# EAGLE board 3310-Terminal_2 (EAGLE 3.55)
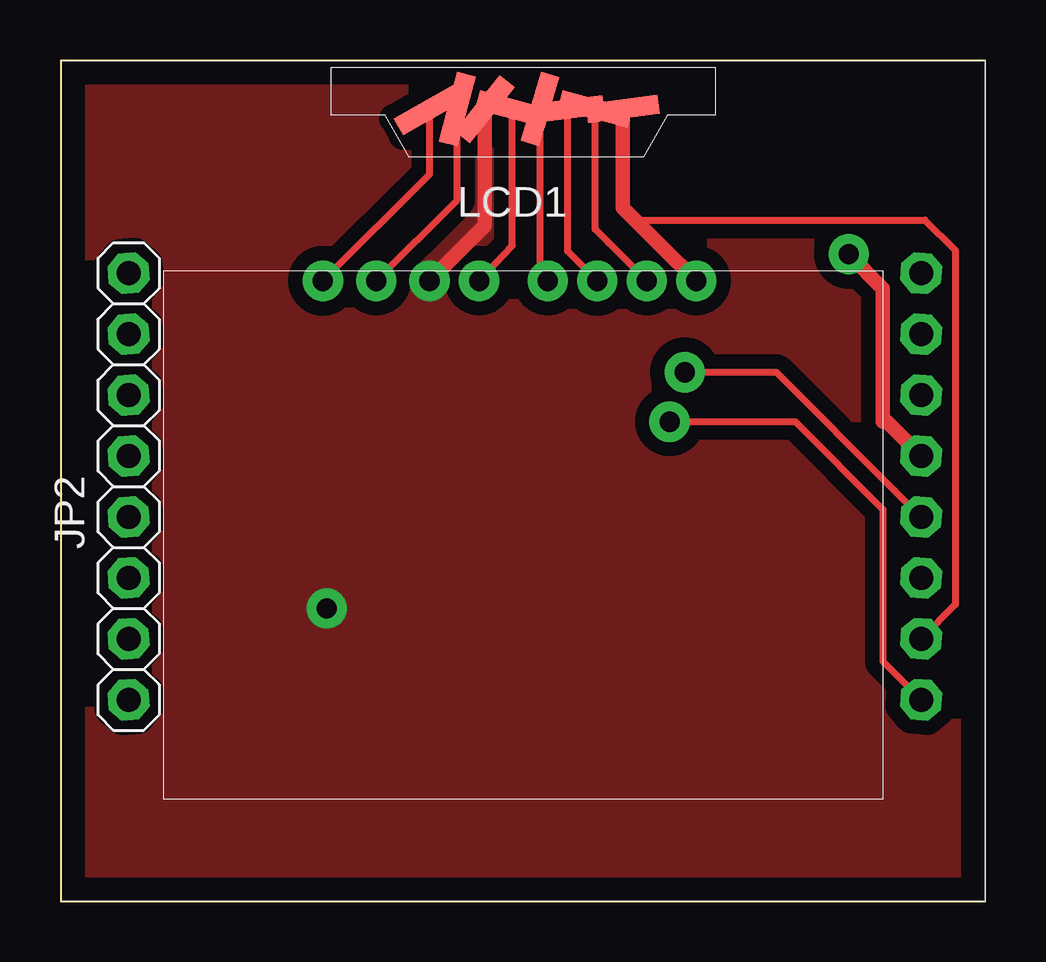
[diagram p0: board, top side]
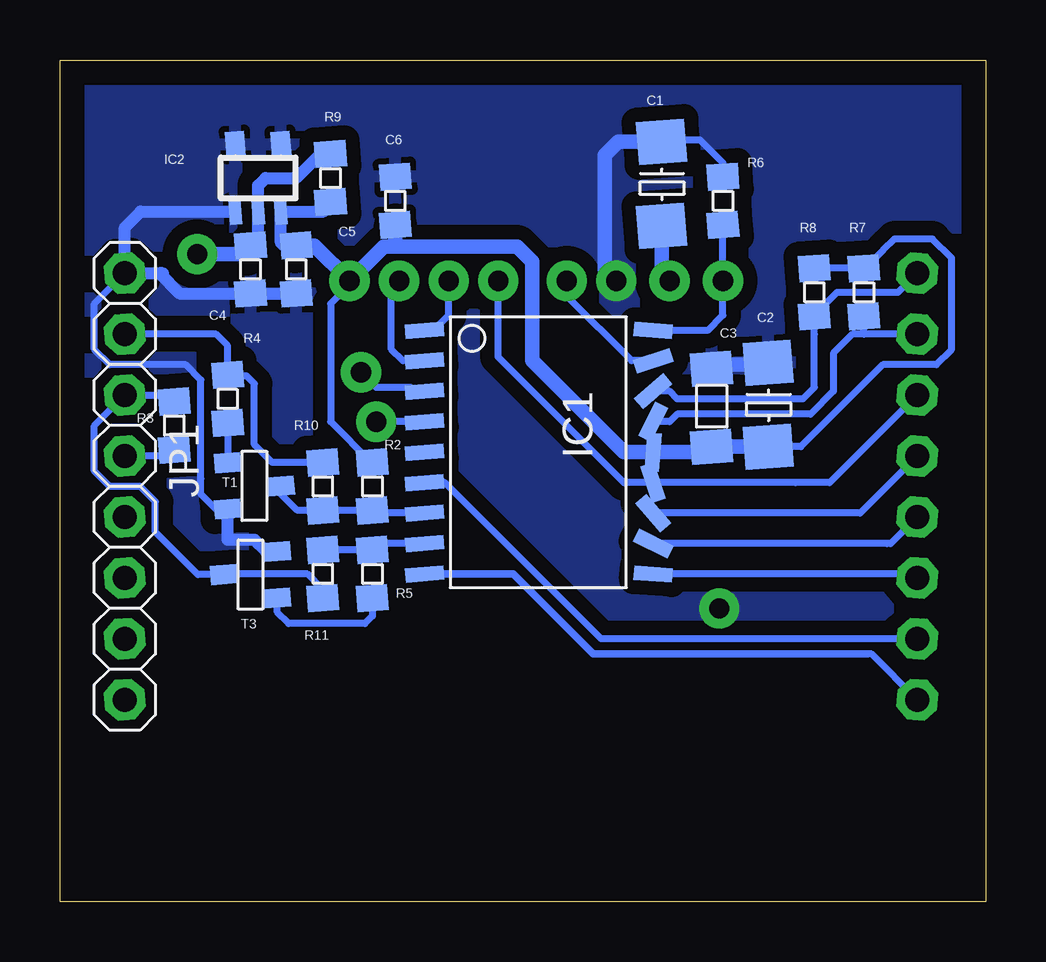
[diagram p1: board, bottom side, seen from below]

Size 38.58 x 35.08 mm. Coordinates in mm from the lower left corner, seen from the top.
Outline: 0,0 38.58,0 38.58,35.08 0,35.08 0,0
Copper layers used: Top, Bottom

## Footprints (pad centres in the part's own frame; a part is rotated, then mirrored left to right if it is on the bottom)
D-ELKA = smd 1.8 x 2 rotated 4.4:  1.824,0.019 | smd 1.8 x 2 rotated 4.3:  -1.676,0.019
D1206 = smd 1.4 x 1.7 rotated 4.4:  1.673,0 | smd 1.4 x 1.7 rotated 4.3:  -1.573,0
D0805 = smd 1.1 x 1.3 rotated 4.3:  -1,0 | smd 1.1 x 1.3 rotated 4.4:  1,0
18 = smd 0.6 x 1.6 rotated 4.3:  -5.08,-5.131;  5.08,4.394 | smd 0.6 x 1.6 rotated 4.4:  -3.81,-5.131 | smd 0.6 x 1.6 rotated 4.5:  -2.54,-5.131 | smd 0.6 x 1.6 rotated 4.6:  -1.27,-5.131 | smd 0.6 x 1.6 rotated 4.7:  0,-5.131;  1.27,-5.131 | smd 0.6 x 1.6 rotated 4.8:  2.54,-5.131 | smd 0.6 x 1.6 rotated 4.9:  3.81,-5.131 | smd 0.6 x 1.6 rotated 5:  5.08,-5.131 | smd 0.6 x 1.6 rotated 26.8:  3.81,4.394 | smd 0.6 x 1.6 rotated 49.3:  2.54,4.394 | smd 0.6 x 1.6 rotated 71.8:  1.27,4.394 | smd 0.6 x 1.6 rotated 94.3:  0,4.394 | smd 0.6 x 1.6 rotated 116.8:  -1.27,4.394 | smd 0.6 x 1.6 rotated 139.3:  -2.54,4.394 | smd 0.6 x 1.6 rotated 161.8:  -3.81,4.394 | smd 0.6 x 1.6 rotated 184.3:  -5.08,4.394
T23/5 = smd 0.5 x 1.1 rotated 4.3:  0.95,1.4 | smd 0.5 x 1.1 rotated 4.4:  0,1.4 | smd 0.5 x 1.1 rotated 4.5:  -0.95,1.4 | smd 0.8 x 1.1 rotated 4.6:  -0.95,-1.4 | smd 0.8 x 1.1 rotated 4.7:  0.95,-1.4
NH1X8 = drill 1 pad 1.7 octagon:  -8.89,0;  -6.35,0;  -3.81,0;  -1.27,0;  1.27,0;  3.81,0;  6.35,0;  8.89,0
10 = smd 0.8 x 3 rotated 97.3: N 2.1,17 | smd 0.8 x 3 rotated 345.1: T -2.5,17 | smd 0.8 x 3 rotated 119.7:  -3.65,17 | smd 0.8 x 3 rotated 321.2:  -1.35,17 | smd 0.8 x 3 rotated 74.8:  -0.2,17;  3.25,17 | smd 0.8 x 3 rotated 343.5:  0.95,17 | smd 0.8 x 3 rotated 97.6:  4.4,17
D23 = smd 0.8 x 1.1 rotated 4.4:  0.991,-0.154 | smd 0.8 x 1.1 rotated 4.3:  -0.94,-0.154 | smd 0.8 x 1.1 rotated 4.5:  0.025,-2.386

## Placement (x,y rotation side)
C1  4,7æ  [D-ELKA]  13.49,29.84 90 bottom
C2  10æ  [D-ELKA]  9.05,20.64 90 bottom
C3  100n  [D1206]  11.43,20.64 270 bottom
C4  100n  [D0805]  30.64,26.35 90 bottom
C5  100n  [D0805]  28.73,26.35 90 bottom
C6  100n  [D0805]  24.61,29.21 270 bottom
IC1  16F628A  [18]  18.26,18.73 270 bottom
IC2  MC78LC33  [T23/5]  30.32,30.16 180 bottom
JP1  PINHD-1X8  [NH1X8]  35.88,17.3 270 bottom
JP2  PINHD-1X8  [NH1X8]  2.86,17.3 90 top
LCD1  3310  [10]  19.05,16.03 0 top
R2  10K  [D0805]  25.56,17.3 90 bottom
R3  10K  [D0805]  33.81,19.84 90 bottom
R4  1,5k  [D0805]  31.59,20.96 90 bottom
R5  10K  [D0805]  25.56,13.65 90 bottom
R6  10K  [D0805]  10.95,29.21 270 bottom
R7  10K  [D0805]  5.08,25.4 90 bottom
R8  10K  [D0805]  7.14,25.4 90 bottom
R9  0R  [D0805]  27.3,30.16 270 bottom
R10  0R  [D0805]  27.62,17.3 270 bottom
R11  0R  [D0805]  27.62,13.65 90 bottom
T1  BC817  [D23]  31.75,17.3 90 bottom
T3  BC817  [D23]  29.37,13.65 270 bottom

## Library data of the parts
C1-C6 IC1 IC2 JP1 JP2 R2-R11 = CONTR1
LCD1 = lcd
T1 T3 = CONTR

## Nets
+3,3V: C2. C3. C5. C6. IC1. IC2. JP1. LCD1. R2. R7. R8. R9.
+5V: C4. IC2. JP1. R3. R9.
GND: C1. C2. C3. C4. C5. C6. IC1. IC2. JP1. LCD1. R6. T1. T3.
N$1: IC1. JP1.
N$3: IC1. JP1.
N$4: IC1. LCD1. R6.
N$5: IC1. LCD1.
N$6: IC1. JP2.
N$7: IC1. LCD1.N
N$8: C1. LCD1.T
N$9: IC1. LCD1.
N$10: IC1. JP2. LCD1.
N$11: IC1. JP2.
N$12: IC1. R2. R10. T1.
N$13: IC1. R5. R11.
N$14: IC1. JP2.
N$15: IC1. JP2.
N$16: R5. T3.
N$17: IC1. JP2.
N$20: JP1. R3. R11. T3.
N$21: R4. T1.
N$22: JP1. R4. R10.
N$23: IC1. JP2. R7.
N$24: IC1. JP2. R8.

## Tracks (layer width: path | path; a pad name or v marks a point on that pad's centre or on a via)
+3,3V  (via drill 0.84 pad 1.68)
  Top 0.3: 23.5,28.89 23.97,28.42 36.04,28.42 37.31,27.15 37.31,12.38 35.88,10.95
  Top 0.6: LCD1. 23.45,28.94 23.5,28.89 25.08,27.3 v26.51,25.88
  Bottom 0.3: 7.14,26.35 | 7.14,26.35 R8. | 7.14,26.35 7.1,26.4 R7. 5.08,26.35 4.29,27.15 | C2. 7.71,18.96 4.29,22.38 2.06,22.38 1.43,23.02 1.43,26.83 2.22,27.62 3.81,27.62 4.29,27.15 | 4.29,27.15 | R2. 25.61,18.3 27.3,20 27.3,24.92 26.35,25.88
  Bottom 0.5: C5. 28.78,27.04 28.89,27.15 29.05,27.15 29.37,27.46 29.37,28.76 27.59,28.76 27.3,29.05 R9.
  Bottom 0.6: C2. 11.36,18.96 11.43,18.89 | 11.43,18.89 11.43,18.96 | 11.43,18.89 11.59,18.73 13.86,18.73 15.08,18.73 15.56,19.21 18.89,22.54 18.89,26.67 19.53,27.3 24.61,27.3 | 24.61,27.3 25.08,27.3 v26.51,25.88 | v26.51,25.88 26.35,25.88 | C5. 27.99,27.35 v26.51,25.88 | v26.51,25.88 | 24.61,27.3 C6.
+5V  (via drill 0.84 pad 1.68)
  Top 0.6: v32.86,26.99 34.29,25.56 34.29,20 34.45,20 35.88,18.57 | 35.88,18.57
  Bottom 0.3: 33.81,18.89 | 33.81,18.84 33.81,18.89 | 35.88,18.57 34.13,18.57 33.81,18.89
  Bottom 0.5: C4. 30.48,27.62 30.32,27.62 30.32,28.26 30.32,28.76 30.32,29.84 30,30.16 28.73,30.16 27.73,31.16 27.3,31.16
  Bottom 0.6: C4. 30.75,27.04 30.8,26.99 v32.86,26.99
GND  (via drill 0.84 pad 1.68)
  Top 0.6: 17.7,33.03 17.7,28.18 v15.4,25.88
  Bottom 0.3: 29.69,14.45 29.54,14.59 29.52,14.59 | 31.6,16.36 32.08,16.36 32.7,16.99 32.7,17.62 | 10.95,30.21 10.95,30.8 11.91,31.75 13.49,31.75 13.51,31.73 13.51,31.67 | 32.7,17.62 32.7,21.75 33.34,22.38 36.51,22.38 37.15,23.02 37.15,24.92 35.88,26.19 | 32.7,17.62 | 35.88,26.19
  Bottom 0.5: 28.73,25.35 30.53,25.35 30.64,25.24 30.64,25.35 33.61,25.35 34.45,26.19 34.29,26.19 | 31.27,28.76 35.21,28.76 35.88,28.1 35.88,26.35 35.72,26.19 | 29.54,14.59 29.99,14.59 30.32,14.92 30.48,15.08 31.59,15.08 31.59,16.35 31.6,16.36 | 35.72,26.19 | 35.72,26.19 35.88,26.19 34.29,26.19 | 34.29,26.19
  Bottom 0.6: C3. 11.43,22.38 9.21,22.38 9.13,22.46 9.07,22.46 | 13.51,31.67 15.32,31.67 15.88,31.11 15.88,26.35 v15.4,25.88
  other vias: 11.11,12.22
  pour Bottom (isolate 0.6): 0.33,0.25 0.33,34.75 38.33,34.75 38.33,0.25
  pour Top (isolate 0.6): 0.32,0.32 0.32,34.77 38.42,34.77 38.42,0.32
N$1  (via drill 0.84 pad 1.68)
  Top 0.3: v26.04,22.07 29.84,22.07 34.77,17.14 35.88,16.03 | 35.88,16.03
  Bottom 0.3: 23.39,21.27 23.81,21.27 23.97,21.43 25.4,21.43 25.72,21.75 v26.04,22.07
N$3  (via drill 0.84 pad 1.68)
  Top 0.3: v25.4,20 30.64,20 34.29,16.35 34.29,10 JP1. | JP1.
  Bottom 0.3: 23.39,20 23.34,20 | 23.34,20 v25.4,20 | 23.34,20
N$4  (via drill 0.84 pad 1.68)
  Top 0.3: v10.95,25.88 | 15.4,33.03 15.4,30.32 v10.95,25.88
  Bottom 0.3: IC1. 11.59,23.81 10.95,24.45 v10.95,25.88 10.95,28.1 | 10.95,28.1 | 10.95,28.1 R6.
  Bottom 0.5: v10.95,25.88
N$5  (via drill 0.84 pad 1.68)
  Top 0.3: 18.85,33.03 18.85,27.35 v17.46,25.88
  Bottom 0.3: v17.46,25.88 17.46,25.24 14.76,22.54 13.86,22.54 13.81,22.54
N$6
  Bottom 0.3: 4.13,14.92 13.86,14.92 | 4.13,14.92 | 2.86,16.03 | 4.13,14.92 3.97,14.92 2.86,16.03
N$7  (via drill 0.84 pad 1.68)
  Top 0.3: LCD1.N 21.15,27.11 v22.38,25.88
  Bottom 0.3: v22.38,25.88 22.38,24.45 23.02,23.81 23.39,23.81
N$8  (via drill 0.84 pad 1.68)
  Top 0.3: LCD1.T 16.55,29.25 v13.18,25.88
  Bottom 0.6: C1. 13.51,26.21 v13.18,25.88
N$9  (via drill 0.84 pad 1.68)
  Top 0.3: 22.3,33.03 22.3,28.02 22.86,27.46 v24.45,25.88
  Bottom 0.3: 23.34,22.54 23.39,22.54 24.29,22.54 24.77,23.02 24.77,25.56 v24.45,25.88 | v24.45,25.88
N$10  (via drill 0.84 pad 1.68)
  Top 0.3: 20,33.03 20,26.19 v20.32,25.88
  Bottom 0.3: v20.32,25.88 20.32,22.7 16.51,18.89 15.08,17.46 13.97,17.46 | 13.81,17.46 | 13.81,17.46 13.86,17.46 13.97,17.46 | 13.81,17.46 7.94,17.46 6.51,17.46 | 13.97,17.46 | 2.86,21.11 | 6.51,17.46 | 6.51,17.46 2.86,21.11
N$11
  Bottom 0.3: 23.39,17.46 22.54,17.46 16.03,10.95 2.86,10.95 | 2.86,10.95
N$12
  Bottom 0.3: 25.56,16.35 | 25.56,16.35 25.56,16.3 27.51,16.3 27.62,16.19 R10. 28.69,16.3 29.53,17.14 29.52,17.15 T1. | 23.39,16.19 25.4,16.19 25.56,16.35
N$13
  Bottom 0.3: 23.39,14.92 25.4,14.92 25.56,14.76 R5. 27.57,14.65 27.62,14.61 R11.
N$14
  Bottom 0.3: 2.86,8.41 | 4.92,10.32 4.76,10.32 2.86,8.41
  Bottom 0.305: 23.39,13.65 19.68,13.65 16.35,10.32 4.92,10.32
N$15
  Bottom 0.3: 2.86,13.49 | 13.86,13.65 3.02,13.65 2.86,13.49
N$16
  Bottom 0.3: 29.52,12.66 29.52,12.06 29.05,11.59 25.88,11.59 25.56,11.91 25.56,12.7 25.56,12.65
N$17
  Bottom 0.3: 5.24,16.19 13.86,16.19 | 2.86,18.57 | 5.24,16.19 | 2.86,18.57 5.24,16.19
N$20
  Bottom 0.3: 27.62,12.65 27.62,13.02 28.26,13.65 31.59,13.65 31.62,13.63 T3. 32.84,13.63 34.61,15.4 34.61,16.67 35.24,17.3 36.51,17.3 37.15,17.94 37.15,19.84 35.88,21.11 | 33.86,20.84 33.97,21.11 35.88,21.11 | 33.86,20.84 R3. | 33.86,20.84 33.81,20.8 | 35.88,21.11
N$21
  Bottom 0.3: 31.59,19.95 31.59,20 31.6,20 31.6,18.29
N$22
  Bottom 0.3: 32.07,23.65 35.88,23.65 | 27.62,18.3 29.73,18.3 30.48,19.05 30.48,21.59 30.8,21.91 31.43,21.91 31.48,21.95 R4. | 32.07,23.65 | 32.07,23.65 31.59,23.18 R4. | R4. 31.59,21.91
  Bottom 0.406: 35.88,23.65
N$23
  Bottom 0.3: 13.86,20 13.18,20 12.86,20.32 7.3,20.32 6.35,21.27 6.35,22.86 5.56,23.65 5.08,23.65 | 5.08,23.65 | 5.08,23.65 5.08,24.4 | 5.08,23.65 | 2.7,23.65 | 2.86,23.65 2.7,23.65 | 2.7,23.65 5.08,23.65 | 2.7,23.65
N$24
  Bottom 0.3: 13.86,21.27 13.18,21.27 12.86,20.95 7.62,20.95 7.14,21.43 7.14,23.65 7.14,24.4 7.14,24.45 6.19,25.4 3.65,25.4 JP2. | JP2.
